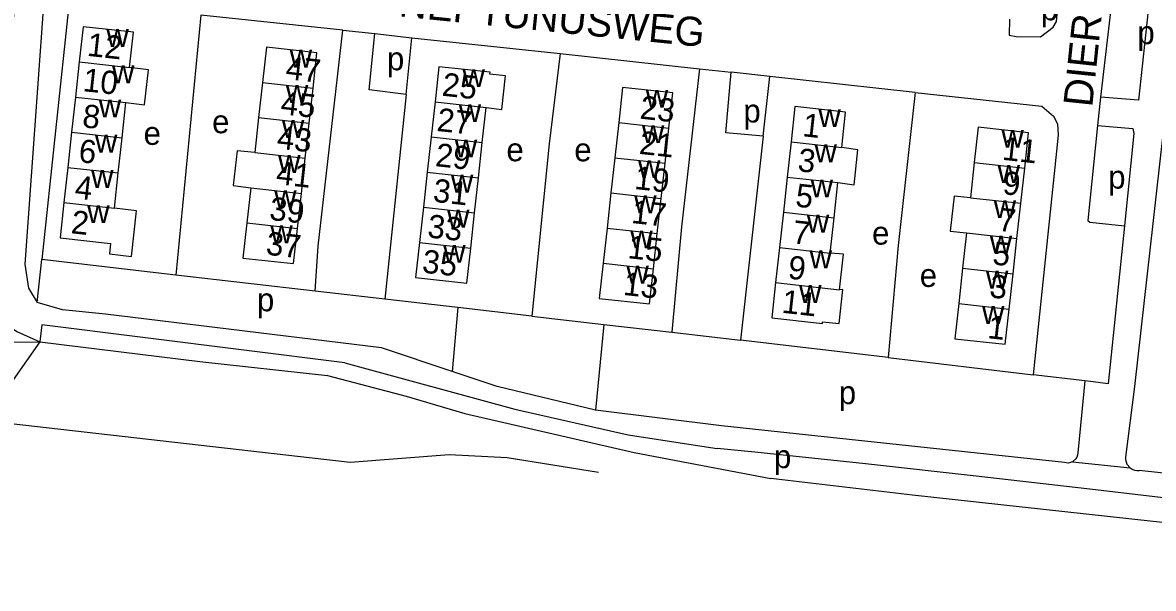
# Model space of a CAD drawing. Extents: x 161936 to 163647, y 386450 to 388633.
# Drawn here: x 162198.4 to 162393, y 386467.7 to 386565 of the extents above; entities that cross this region are included whole.
import ezdxf

# ---------------------------------------------------------------- set-up
doc = ezdxf.new("R2010")
doc.units = 0
for name, color, linetype in [('BLT_Basislijn', 7, 'Continuous'), ('BLT_Bebouwing', 7, 'Continuous'), ('BLT_Centroide', 7, 'Continuous'), ('BLT_Huisnummer', 7, 'Continuous'), ('BLT_Huisnummer_ tussenligend', 7, 'Continuous'), ('BLT_Onderverdeling_panden', 7, 'Continuous'), ('BLT_Straatnaam', 7, 'Continuous'), ('BLT_Vlakafsluiter', 7, 'Continuous')]:
    doc.layers.add(name, color=color, linetype=linetype)

msp = doc.modelspace()

# ---------------------------------------------------------------- linework, layer by layer
at = {"layer": 'BLT_Basislijn'}
for p, q in [((162386.66, 386576.12), (162383.94, 386552.2)), ((162206.46, 386568.55), (162201.73, 386524.26)), ((162229.09, 386566.3), (162224.79, 386521.59)), ((162253.55, 386563.71), (162229.09, 386566.3)), ((162253.55, 386563.71), (162259.02, 386563.14)), ((162259.02, 386563.14), (162265.42, 386562.44)), ((162264.44, 386552.65), (162265.42, 386562.44)), ((162265.42, 386562.44), (162290.93, 386559.72)), ((162290.93, 386559.72), (162314.91, 386557.1)), ((162314.91, 386557.1), (162320.36, 386556.51)), ((162327.03, 386555.76), (162320.36, 386556.51)), ((162325.84, 386545.49), (162327.03, 386555.76)), ((162352.01, 386553), (162327.03, 386555.76)), ((162264.44, 386552.65), (162260.78, 386517.46)), ((162383.94, 386552.2), (162383.4, 386547.33)), ((162325.84, 386545.49), (162321.96, 386510.39)), ((162394.6, 386545.27), (162389.79, 386502.39)), ((162388.02, 386530.04), (162385.21, 386502.89)), ((162200.96, 386516.89), (162201.73, 386524.26)), ((162224.79, 386521.59), (162201.73, 386524.26)), ((162248.76, 386518.8), (162224.79, 386521.59)), ((162260.78, 386517.46), (162248.76, 386518.8)), ((162273.31, 386515.99), (162260.78, 386517.46)), ((162273.31, 386515.99), (162272.37, 386505)), ((162286.08, 386514.49), (162273.31, 386515.99)), ((162253.9, 386506.5), (162201.74, 386513.02)), ((162286.08, 386514.49), (162298.45, 386513.08)), ((162298.45, 386513.08), (162296.99, 386498.36)), ((162298.45, 386513.08), (162310.18, 386511.75)), ((162310.18, 386511.75), (162321.96, 386510.39)), ((162347.35, 386507.4), (162321.96, 386510.39)), ((162347.35, 386507.4), (162372.3, 386504.43)), ((162381.24, 386503.38), (162372.3, 386504.43)), ((162381.24, 386503.38), (162380.7, 386498.03)), ((162382.21, 386503.26), (162381.24, 386503.38)), ((162385.21, 386502.89), (162382.21, 386503.26)), ((162389.79, 386502.39), (162388.2, 386490.26)), ((162318.71, 386495.63), (162296.99, 386498.36)), ((162380.7, 386498.03), (162379.99, 386490.98)), ((162379.09, 386489.44), (162389, 386488.41)), ((162417.32, 386485.01), (162390.56, 386487.92)), ((162496.07, 386467.66), (162392.98, 386479.18))]:
    msp.add_line(p, q, dxfattribs=at)
for points in [[(162197.9, 386575.94), (162197.18, 386569.42), (162196.75, 386565.1), (162193.24, 386523.1), (162193.3, 386518.94), (162194.13, 386515.05), (162195.35, 386513.36), (162197.45, 386511.86), (162201.4, 386510.1)], [(162386.66, 386576.12), (162392.95, 386575.15), (162390.45, 386551.71), (162383.94, 386552.2)], [(162368.28, 386565.61), (162368.18, 386562.89), (162369.39, 386562.62), (162373.59, 386562.6), (162375.76, 386564.26), (162376.33, 386565.21), (162377.03, 386572.33)], [(162202.09, 386568.96), (162198.8, 386523.45), (162199.46, 386519.34), (162200.96, 386516.89)], [(162248.76, 386518.8), (162249.32, 386526.57), (162253.55, 386563.71)], [(162264.44, 386552.65), (162258.05, 386553.44), (162259.02, 386563.14)], [(162290.93, 386559.72), (162289.05, 386544.19), (162286.08, 386514.49)], [(162314.91, 386557.1), (162311.83, 386529.91), (162310.18, 386511.75)], [(162325.84, 386545.49), (162319.42, 386546.08), (162320.36, 386556.51)], [(162352.01, 386553), (162349.11, 386526.7), (162347.35, 386507.4)], [(162352.01, 386553), (162373.79, 386550.64), (162375.85, 386548.91), (162376.49, 386547.63), (162376.6, 386545.67), (162372.3, 386504.43)], [(162383.4, 386547.33), (162381.72, 386530.98), (162382.09, 386530.67), (162388.02, 386530.04)], [(162383.4, 386547.33), (162389.46, 386546.82), (162389.62, 386545.93), (162388.02, 386530.04)], [(162272.37, 386505), (162260.22, 386509.08), (162212.72, 386514.86), (162205.32, 386515.59), (162200.96, 386516.89)], [(162201.74, 386513.02), (162201.4, 386510.1)], [(162201.4, 386510.1), (162228.92, 386506.7), (162250.91, 386504.29), (162264.45, 386500.77), (162274.51, 386497.76), (162303.69, 386491.05), (162327.18, 386486.57)], [(162253.9, 386506.5), (162283.15, 386498.48), (162302.63, 386494.07), (162317.93, 386491.75)], [(162296.99, 386498.36), (162280.09, 386502.4), (162272.37, 386505)], [(162191.86, 386496.54), (162254.82, 386489.39), (162271.86, 386490.73), (162281.84, 386490.2), (162297.53, 386487.69)], [(162377.69, 386489.32), (162325.63, 386494.9), (162318.71, 386495.63)], [(162400.62, 386482.55), (162381.58, 386484.8), (162362.54, 386486.98), (162343.48, 386489.07), (162324.42, 386491.08), (162317.93, 386491.75)], [(162379.09, 386489.44), (162378.75, 386489.3), (162378.38, 386489.23), (162378.01, 386489.24), (162377.69, 386489.32)], [(162379.99, 386490.98), (162379.95, 386490.61), (162379.84, 386490.25), (162379.65, 386489.93), (162379.09, 386489.44)], [(162388.2, 386490.26), (162388.21, 386489.84), (162388.3, 386489.43), (162388.47, 386489.05), (162389, 386488.41)], [(162389, 386488.41), (162389.35, 386488.18), (162389.74, 386488.01), (162390.14, 386487.93), (162390.56, 386487.92)], [(162392.98, 386479.18), (162351.57, 386483.73), (162327.18, 386486.57)]]:
    msp.add_lwpolyline(points, dxfattribs=at)
at = {"layer": 'BLT_Bebouwing'}
for p, q in [((162208.18, 386558.28), (162207.52, 386552.22)), ((162239.71, 386554.74), (162239.04, 386548.69)), ((162247.74, 386547.73), (162248.41, 386553.77)), ((162207.52, 386552.22), (162206.86, 386546.16)), ((162215.55, 386545.22), (162216.21, 386551.27)), ((162269.4, 386551.4), (162268.73, 386545.35)), ((162277.54, 386544.38), (162278.21, 386550.43)), ((162239.04, 386548.69), (162238.37, 386542.65)), ((162247.07, 386541.68), (162247.74, 386547.73)), ((162301.01, 386547.83), (162300.34, 386541.78)), ((162206.86, 386546.16), (162206.2, 386540.11)), ((162308.99, 386540.83), (162309.65, 386546.88)), ((162214.89, 386539.16), (162215.55, 386545.22)), ((162268.73, 386545.35), (162268.07, 386539.3)), ((162276.88, 386538.33), (162277.54, 386544.38)), ((162330.67, 386544.51), (162330.01, 386538.45)), ((162300.34, 386541.78), (162299.67, 386535.73)), ((162206.2, 386540.11), (162205.55, 386534.05)), ((162246.4, 386535.64), (162247.07, 386541.68)), ((162308.32, 386534.77), (162308.99, 386540.83)), ((162362.19, 386540.96), (162361.52, 386534.89)), ((162370.2, 386533.93), (162370.87, 386540)), ((162214.23, 386533.1), (162214.89, 386539.16)), ((162268.07, 386539.3), (162267.4, 386533.26)), ((162276.21, 386532.29), (162276.88, 386538.33)), ((162330.01, 386538.45), (162329.34, 386532.4)), ((162237.7, 386536.61), (162237.03, 386530.56)), ((162338.06, 386531.44), (162338.72, 386537.5)), ((162245.73, 386529.6), (162246.4, 386535.64)), ((162299.67, 386535.73), (162299.01, 386529.67)), ((162307.65, 386528.72), (162308.32, 386534.77)), ((162267.4, 386533.26), (162266.73, 386527.21)), ((162275.54, 386526.24), (162276.21, 386532.29)), ((162329.34, 386532.4), (162328.68, 386526.34)), ((162369.53, 386527.87), (162370.2, 386533.93)), ((162337.39, 386525.38), (162338.06, 386531.44)), ((162299.01, 386529.67), (162298.34, 386523.62)), ((162306.99, 386522.67), (162307.65, 386528.72)), ((162360.86, 386528.83), (162360.18, 386522.76)), ((162328.68, 386526.34), (162328.01, 386520.28)), ((162368.86, 386521.8), (162369.53, 386527.87)), ((162360.18, 386522.76), (162359.52, 386516.7)), ((162368.19, 386515.74), (162368.86, 386521.8))]:
    msp.add_line(p, q, dxfattribs=at)
for points in [[(162216.86, 386557.33), (162217.52, 386563.39), (162208.84, 386564.33), (162208.18, 386558.28)], [(162248.41, 386553.77), (162249.08, 386559.82), (162240.38, 386560.78), (162239.71, 386554.74)], [(162216.21, 386551.27), (162219.44, 386550.9), (162220.09, 386556.89), (162216.86, 386557.33)], [(162278.21, 386550.43), (162280.9, 386550.06), (162281.54, 386555.85), (162278.84, 386556.15), (162278.87, 386556.48), (162270.07, 386557.45), (162269.4, 386551.4)], [(162309.65, 386546.88), (162310.32, 386552.93), (162301.67, 386553.88), (162301.01, 386547.83)], [(162339.39, 386543.56), (162340.05, 386549.61), (162331.34, 386550.57), (162330.67, 386544.51)], [(162370.87, 386540), (162371.54, 386546.07), (162362.86, 386547.02), (162362.19, 386540.96)], [(162238.37, 386542.65), (162235.34, 386542.98), (162234.68, 386536.97), (162237.7, 386536.61)], [(162338.72, 386537.5), (162341.5, 386537.14), (162342.16, 386543.16), (162339.39, 386543.56)], [(162205.55, 386534.05), (162204.89, 386527.99), (162213.57, 386527.04), (162213.38, 386525.22), (162217.16, 386524.8), (162218.02, 386532.64), (162214.23, 386533.1)], [(162361.52, 386534.89), (162358.74, 386535.15), (162358.07, 386529.13), (162360.86, 386528.83)], [(162237.03, 386530.56), (162236.36, 386524.52), (162245.06, 386523.55), (162245.73, 386529.6)], [(162266.73, 386527.21), (162266.07, 386521.15), (162274.88, 386520.18), (162275.54, 386526.24)], [(162339.02, 386519.07), (162339.69, 386525.17), (162337.39, 386525.38)], [(162298.34, 386523.62), (162297.67, 386517.56), (162306.32, 386516.61), (162306.99, 386522.67)], [(162328.01, 386520.28), (162327.34, 386514.22), (162336.06, 386513.26), (162336.09, 386513.54), (162338.94, 386513.22), (162339.59, 386519.09), (162339.02, 386519.07)], [(162359.52, 386516.7), (162358.85, 386510.63), (162367.52, 386509.67), (162368.19, 386515.74)]]:
    msp.add_lwpolyline(points, dxfattribs=at)
at = {"layer": 'BLT_Onderverdeling_panden'}
for p, q in [((162208.18, 386558.28), (162216.86, 386557.33)), ((162239.71, 386554.74), (162248.41, 386553.77)), ((162207.52, 386552.22), (162216.21, 386551.27)), ((162269.4, 386551.4), (162278.21, 386550.43)), ((162239.04, 386548.69), (162247.74, 386547.73)), ((162301.01, 386547.83), (162309.65, 386546.88)), ((162206.86, 386546.16), (162215.55, 386545.22)), ((162268.73, 386545.35), (162277.54, 386544.38)), ((162330.67, 386544.51), (162339.39, 386543.56)), ((162238.37, 386542.65), (162247.07, 386541.68)), ((162300.34, 386541.78), (162308.99, 386540.83)), ((162206.2, 386540.11), (162214.89, 386539.16)), ((162362.19, 386540.96), (162370.87, 386540)), ((162268.07, 386539.3), (162276.88, 386538.33)), ((162330.01, 386538.45), (162338.72, 386537.5)), ((162237.7, 386536.61), (162246.4, 386535.64)), ((162205.55, 386534.05), (162214.23, 386533.1)), ((162299.67, 386535.73), (162308.32, 386534.77)), ((162361.52, 386534.89), (162370.2, 386533.93)), ((162267.4, 386533.26), (162276.21, 386532.29)), ((162329.34, 386532.4), (162338.06, 386531.44)), ((162237.03, 386530.56), (162245.73, 386529.6)), ((162299.01, 386529.67), (162307.65, 386528.72)), ((162360.86, 386528.83), (162369.53, 386527.87)), ((162266.73, 386527.21), (162275.54, 386526.24)), ((162328.68, 386526.34), (162337.39, 386525.38)), ((162298.34, 386523.62), (162306.99, 386522.67)), ((162360.18, 386522.76), (162368.86, 386521.8)), ((162328.01, 386520.28), (162339.02, 386519.07)), ((162359.52, 386516.7), (162368.19, 386515.74))]:
    msp.add_line(p, q, dxfattribs=at)
at = {"layer": 'BLT_Vlakafsluiter'}
for p, q in [((162180.67, 386509.86), (162201.4, 386510.1)), ((162201.4, 386510.1), (162191.86, 386496.54))]:
    msp.add_line(p, q, dxfattribs=at)

# ---------------------------------------------------------------- texts
at = {"layer": 'BLT_Centroide'}
for s, p in [('p', (162373.64, 386565.43)), ('w', (162212.85, 386560.84)), ('p', (162390.26, 386561.33)), ('w', (162244.39, 386557.28)), ('p', (162261.14, 386556.83)), ('w', (162213.81, 386554.59)), ('w', (162274.13, 386553.94)), ('w', (162243.73, 386551.22)), ('w', (162305.66, 386550.38)), ('w', (162211.54, 386548.72)), ('w', (162273.47, 386547.91)), ('p', (162322.47, 386547.84)), ('w', (162335.37, 386547.06)), ('e', (162231.05, 386545.99)), ('w', (162243.05, 386545.19)), ('w', (162210.88, 386542.66)), ('e', (162219.26, 386543.99)), ('w', (162305, 386544.31)), ('w', (162366.86, 386543.5)), ('w', (162272.8, 386541.84)), ('e', (162281.69, 386541.17)), ('e', (162293.37, 386541.16)), ('w', (162334.7, 386541)), ('w', (162242.39, 386539.16)), ('w', (162304.33, 386538.28)), ('w', (162366.2, 386537.44)), ('w', (162210.22, 386536.59)), ('w', (162272.13, 386535.78)), ('w', (162334.03, 386534.94)), ('p', (162385.24, 386536.46)), ('w', (162241.72, 386533.09)), ('w', (162303.66, 386532.22)), ('w', (162365.53, 386531.38)), ('w', (162209.55, 386530.53)), ('w', (162271.47, 386529.75)), ('w', (162241.05, 386527.06)), ('w', (162333.37, 386528.88)), ('w', (162303, 386526.16)), ('e', (162344.61, 386526.82)), ('w', (162364.86, 386525.31)), ('w', (162270.8, 386523.69)), ('w', (162333.85, 386522.75)), ('w', (162302.33, 386520.12)), ('e', (162352.81, 386519.54)), ('w', (162364.19, 386519.25)), ('p', (162238.77, 386515.35)), ('w', (162332.04, 386516.78)), ('w', (162363.52, 386513.19)), ('p', (162338.88, 386499.37)), ('p', (162327.73, 386488.36))]:
    msp.add_text(s, height=4, dxfattribs=at).set_placement(p)
at = {"layer": 'BLT_Huisnummer'}
for s, rotation, p in [('12', 353.7858, (162209.41, 386559.33)), ('47', 353.6714, (162243.58, 386555.32)), ('10', 353.7851, (162208.68, 386553.25)), ('25', 353.7098, (162270.49, 386552.47)), ('23', 353.7158, (162304.53, 386548.52)), ('1', 353.7356, (162332.52, 386545.49)), ('6', 353.7851, (162207.95, 386541.04)), ('29', 353.7155, (162269.34, 386540.34)), ('11', 353.704, (162366.88, 386541.44)), ('41', 353.6649, (162241.93, 386537.25)), ('5', 353.7348, (162331.3, 386533.38)), ('17', 353.7165, (162303.07, 386530.56)), ('2', 353.7865, (162206.66, 386528.79)), ('37', 353.6656, (162240.19, 386525.11)), ('5', 353.6975, (162365.21, 386523.43)), ('35', 353.7169, (162267.07, 386522.02)), ('13', 353.7165, (162301.67, 386518.18)), ('11', 353.7356, (162328.95, 386515.11)), ('1', 353.6975, (162364.36, 386510.74))]:
    msp.add_text(s, height=4, rotation=rotation, dxfattribs=at).set_placement(p)
at = {"layer": 'BLT_Huisnummer_ tussenligend'}
for s, rotation, p in [('45', 353.6649, (162242.71, 386549.29)), ('8', 353.7851, (162208.6, 386547.04)), ('27', 353.7155, (162269.59, 386546.4)), ('43', 353.6649, (162242.06, 386543.36)), ('21', 353.7151, (162304.41, 386542.46)), ('3', 353.7356, (162331.69, 386539.47)), ('19', 353.7151, (162303.6, 386536.41)), ('4', 353.7865, (162207.29, 386534.79)), ('31', 353.7169, (162268.93, 386534.22)), ('9', 353.6968, (162366.95, 386535.54)), ('39', 353.6656, (162240.78, 386531.1)), ('7', 353.6968, (162366.16, 386529.22)), ('33', 353.7169, (162267.97, 386528.08)), ('7', 353.7348, (162330.77, 386527.06)), ('15', 353.7165, (162302.44, 386524.5)), ('9', 353.7348, (162330.01, 386520.99)), ('3', 353.6975, (162364.69, 386517.76))]:
    msp.add_text(s, height=4, rotation=rotation, dxfattribs=at).set_placement(p)
at = {"layer": 'BLT_Straatnaam'}
for s, height, rotation, p in [('DIERENRIEMSTRAAT', 5, 84.0401, (162382.48, 386550.38)), ('NEPTUNUSWEG', 4.9999, 354.2204, (162263.09, 386566.12))]:
    msp.add_text(s, height=height, rotation=rotation, dxfattribs=at).set_placement(p)

doc.saveas('drawing.dxf')
